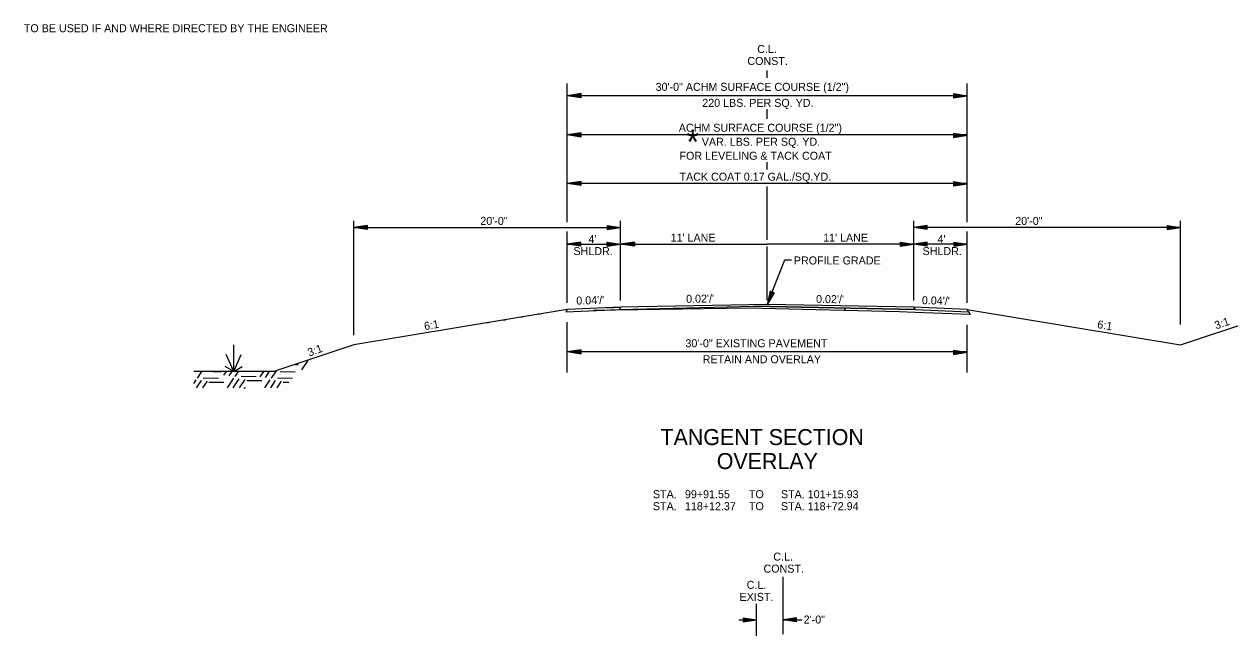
# Model space of a CAD drawing. Extents: x -900 to 15312, y 1857 to 2945.
# Drawn here: x 1572 to 2476, y 2439 to 2897 of the extents above; entities that cross this region are included whole.
import ezdxf

# ---------------------------------------------------------------- set-up
doc = ezdxf.new("R2010")
doc.units = 0
for name, color, linetype in [('R_Annotation', 7, 'Continuous'), ('R_Centerline', 7, 'Continuous'), ('R_Dimension', 7, 'Continuous'), ('R_Draft', 7, 'Continuous')]:
    doc.layers.add(name, color=color, linetype=linetype)

msp = doc.modelspace()

# ---------------------------------------------------------------- linework, layer by layer
at = {"layer": 'R_Annotation'}
for p, q in [((2239.93, 2683.31), (2119.09, 2685.72)), ((2239.09, 2684.99), (2129.09, 2687.19)), ((1979.08, 2683.39), (1819.08, 2656.72)), ((2009.09, 2684.59), (2019.09, 2684.99)), ((2019.09, 2684.99), (2018.23, 2683.27)), ((2279.09, 2683.39), (2239.09, 2684.99)), ((2239.09, 2684.99), (2239.93, 2683.31)), ((2279.09, 2683.39), (2439.09, 2656.72)), ((2439.09, 2656.72), (2499.09, 2676.72)), ((1819.08, 2656.72), (1759.08, 2636.72)), ((1759.08, 2636.72), (1699.08, 2636.72))]:
    msp.add_line(p, q, dxfattribs=at)
for points in [[(1939.32, 2676.76), (1939.32, 2676.75), (1939.32, 2676.72), (1939.32, 2676.7), (1939.32, 2676.69)], [(1939.38, 2676.69), (1939.38, 2676.7), (1939.38, 2676.73), (1939.38, 2676.75), (1939.39, 2676.77)], [(1945.88, 2677.86), (1945.83, 2677.84), (1945.5, 2677.73), (1945.17, 2677.65), (1944.75, 2677.62), (1944.63, 2677.62), (1944.5, 2677.63)], [(1947, 2677.97), (1947.02, 2677.97), (1947.04, 2677.97), (1947.06, 2677.97)], [(1957.24, 2679.73), (1957.22, 2679.73), (1957.17, 2679.73), (1957.13, 2679.73), (1957.12, 2679.73)], [(1958.72, 2680), (1958.64, 2679.96), (1958.28, 2679.84), (1957.91, 2679.74), (1957.5, 2679.72), (1957.37, 2679.72), (1957.24, 2679.73)], [(1959.57, 2680.14), (1959.64, 2680.14), (1959.72, 2680.14), (1959.8, 2680.13)], [(1964.92, 2681.03), (1964.92, 2681.03), (1964.92, 2681.03), (1964.92, 2681.03)], [(1964.98, 2681.03), (1964.98, 2681.03), (1964.98, 2681.04), (1964.98, 2681.04)], [(1970.83, 2682.01), (1970.78, 2682.01), (1970.73, 2682), (1970.68, 2681.99)], [(1972.6, 2682.31), (1972.6, 2682.31), (1972.6, 2682.31), (1972.6, 2682.31)], [(1972.6, 2682.31), (1972.62, 2682.31), (1972.64, 2682.31), (1972.66, 2682.31)], [(1913.7, 2672.49), (1913.71, 2672.45), (1913.72, 2672.41), (1913.72, 2672.36), (1913.72, 2672.36), (1913.72, 2672.35)], [(1920.55, 2673.64), (1920.42, 2673.57), (1920.28, 2673.51), (1919.86, 2673.38), (1919.57, 2673.31), (1919.14, 2673.28), (1918.9, 2673.28), (1918.68, 2673.3), (1918.59, 2673.31)], [(1921.4, 2673.63), (1921.42, 2673.63), (1921.44, 2673.63), (1921.46, 2673.63)], [(1931.64, 2675.39), (1931.62, 2675.39), (1931.46, 2675.39), (1931.31, 2675.4), (1931.19, 2675.41)], [(1933.36, 2675.77), (1933.2, 2675.69), (1933.05, 2675.62), (1932.6, 2675.48), (1932.31, 2675.4), (1931.9, 2675.38), (1931.77, 2675.38), (1931.64, 2675.39)], [(2346.47, 2672.01), (2346.46, 2672.02), (2346.43, 2672.08), (2346.41, 2672.13), (2346.4, 2672.17)]]:
    msp.add_open_spline(points, degree=3, dxfattribs=at)
at = {"layer": 'R_Centerline'}
for p, q in [((2129.09, 2857.11), (2129.09, 2862.4)), ((2129.09, 2826.19), (2129.09, 2833.59)), ((2129.09, 2788.18), (2129.09, 2793.83)), ((2129.09, 2735.56), (2129.09, 2775.55)), ((2129.09, 2690.25), (2129.09, 2730.54)), ((2141.18, 2439.91), (2141.18, 2482.86)), ((2121.18, 2438.65), (2121.18, 2462.72))]:
    msp.add_line(p, q, dxfattribs=at)
at = {"layer": 'R_Dimension'}
for p, q in [((1979.08, 2748.81), (1979.08, 2852.68)), ((2279.09, 2748.81), (2279.09, 2852.68)), ((1989.49, 2845.16), (1979.08, 2843.6)), ((2279.09, 2843.6), (1979.08, 2843.6)), ((1989.49, 2842.04), (1979.08, 2843.6)), ((1989.49, 2844.9), (1980.82, 2843.6)), ((1989.49, 2842.3), (1980.82, 2843.6)), ((1989.49, 2844.63), (1982.61, 2843.6)), ((1989.49, 2842.57), (1982.61, 2843.6)), ((1989.49, 2844.37), (1984.34, 2843.6)), ((1989.49, 2842.83), (1984.34, 2843.6)), ((1989.49, 2844.11), (1986.11, 2843.6)), ((1989.49, 2843.1), (1986.11, 2843.6)), ((1989.49, 2843.84), (1987.84, 2843.6)), ((1989.49, 2843.36), (1987.84, 2843.6)), ((1989.49, 2842.04), (1989.49, 2845.16)), ((2268.68, 2845.16), (2279.09, 2843.6)), ((2268.68, 2845.16), (2268.68, 2842.04)), ((2268.68, 2844.9), (2277.35, 2843.6)), ((2268.68, 2844.63), (2275.56, 2843.6)), ((2268.68, 2844.37), (2273.83, 2843.6)), ((2268.68, 2844.1), (2272.06, 2843.6)), ((2268.68, 2843.84), (2270.32, 2843.6)), ((2268.68, 2842.04), (2279.09, 2843.6)), ((2268.68, 2843.09), (2272.06, 2843.6)), ((2268.68, 2842.57), (2275.56, 2843.6)), ((2268.68, 2842.3), (2277.35, 2843.6)), ((2268.68, 2842.83), (2273.83, 2843.6)), ((2268.68, 2843.36), (2270.32, 2843.6)), ((1989.49, 2815.75), (1979.08, 2814.19)), ((2279.09, 2814.19), (1979.08, 2814.19)), ((1989.49, 2812.63), (1979.08, 2814.19)), ((1989.49, 2815.49), (1980.82, 2814.19)), ((1989.49, 2812.89), (1980.82, 2814.19)), ((1989.49, 2815.22), (1982.61, 2814.19)), ((1989.49, 2813.16), (1982.61, 2814.19)), ((1989.49, 2814.96), (1984.34, 2814.19)), ((1989.49, 2813.42), (1984.34, 2814.19)), ((1989.49, 2814.7), (1986.11, 2814.19)), ((1989.49, 2813.69), (1986.11, 2814.19)), ((1989.49, 2814.43), (1987.84, 2814.19)), ((1989.49, 2813.95), (1987.84, 2814.19)), ((1989.49, 2812.63), (1989.49, 2815.75)), ((2268.81, 2815.51), (2279.21, 2813.94)), ((2268.81, 2815.51), (2268.81, 2812.38)), ((2268.81, 2815.25), (2277.47, 2813.94)), ((2268.81, 2814.97), (2275.68, 2813.94)), ((2268.81, 2814.71), (2273.96, 2813.94)), ((2268.81, 2814.44), (2272.19, 2813.94)), ((2268.81, 2814.18), (2270.45, 2813.94)), ((2268.81, 2812.38), (2279.21, 2813.94)), ((2268.81, 2813.43), (2272.19, 2813.94)), ((2268.81, 2812.91), (2275.68, 2813.94)), ((2268.81, 2812.64), (2277.47, 2813.94)), ((2268.81, 2813.17), (2273.96, 2813.94)), ((2268.81, 2813.71), (2270.45, 2813.94)), ((1989.49, 2779.4), (1979.08, 2777.84)), ((1989.49, 2776.28), (1979.08, 2777.84)), ((2279.09, 2777.84), (1979.08, 2777.84)), ((1989.49, 2779.14), (1980.82, 2777.84)), ((1989.49, 2776.54), (1980.82, 2777.84)), ((1989.49, 2778.87), (1982.61, 2777.84)), ((1989.49, 2776.81), (1982.61, 2777.84)), ((1989.49, 2778.61), (1984.34, 2777.84)), ((1989.49, 2777.07), (1984.34, 2777.84)), ((1989.49, 2778.35), (1986.11, 2777.84)), ((1989.49, 2777.34), (1986.11, 2777.84)), ((1989.49, 2778.08), (1987.84, 2777.84)), ((1989.49, 2777.6), (1987.84, 2777.84)), ((1989.49, 2776.28), (1989.49, 2779.4)), ((2019.09, 2777.84), (2017.82, 2777.84)), ((2268.68, 2779.16), (2279.09, 2777.6)), ((2268.68, 2779.16), (2268.68, 2776.04)), ((2268.68, 2778.9), (2277.35, 2777.6)), ((2268.68, 2778.63), (2275.56, 2777.6)), ((2268.68, 2778.37), (2273.83, 2777.6)), ((2268.68, 2778.1), (2272.06, 2777.6)), ((2268.68, 2777.84), (2270.32, 2777.6)), ((2268.68, 2776.04), (2279.09, 2777.6)), ((2268.68, 2777.09), (2272.06, 2777.6)), ((2268.68, 2776.57), (2275.56, 2777.6)), ((2268.68, 2776.3), (2277.35, 2777.6)), ((2268.68, 2776.83), (2273.83, 2777.6)), ((2268.68, 2777.36), (2270.32, 2777.6)), ((1819.08, 2664.19), (1819.08, 2749.82)), ((2019.09, 2732.32), (2019.09, 2749.82)), ((2239.09, 2732.32), (2239.09, 2749.82)), ((2439.09, 2671.99), (2439.09, 2749.82)), ((1829.08, 2746.32), (1819.08, 2744.82)), ((1829.08, 2743.32), (1819.08, 2744.82)), ((1819.08, 2744.82), (2019.09, 2744.82)), ((1829.08, 2746.07), (1820.75, 2744.82)), ((1829.08, 2743.57), (1820.75, 2744.82)), ((1829.08, 2745.82), (1822.47, 2744.82)), ((1829.08, 2743.83), (1822.47, 2744.82)), ((1829.08, 2745.57), (1824.14, 2744.82)), ((1829.08, 2744.08), (1824.14, 2744.82)), ((1829.08, 2745.31), (1825.83, 2744.82)), ((1829.08, 2744.33), (1825.83, 2744.82)), ((1829.08, 2745.06), (1827.5, 2744.82)), ((1829.08, 2744.59), (1827.5, 2744.82)), ((1829.08, 2746.32), (1829.08, 2743.32)), ((1979.08, 2688.4), (1979.08, 2741.68)), ((2009.09, 2746.32), (2019.09, 2744.82)), ((2009.09, 2746.32), (2009.09, 2743.32)), ((2009.09, 2746.07), (2017.42, 2744.82)), ((2009.09, 2745.82), (2015.7, 2744.82)), ((2009.09, 2745.57), (2014.03, 2744.82)), ((2009.09, 2745.31), (2012.34, 2744.82)), ((2009.09, 2745.06), (2010.67, 2744.82)), ((2009.09, 2743.32), (2019.09, 2744.82)), ((2009.09, 2744.33), (2012.34, 2744.82)), ((2009.09, 2743.83), (2015.7, 2744.82)), ((2009.09, 2743.57), (2017.42, 2744.82)), ((2009.09, 2744.08), (2014.03, 2744.82)), ((2009.09, 2744.59), (2010.67, 2744.82)), ((2249.09, 2746.32), (2239.09, 2744.82)), ((2249.09, 2743.32), (2239.09, 2744.82)), ((2439.09, 2744.82), (2239.09, 2744.82)), ((2249.09, 2746.07), (2240.76, 2744.82)), ((2249.09, 2743.57), (2240.76, 2744.82)), ((2249.09, 2745.82), (2242.48, 2744.82)), ((2249.09, 2743.83), (2242.48, 2744.82)), ((2249.09, 2745.57), (2244.14, 2744.82)), ((2249.09, 2744.08), (2244.14, 2744.82)), ((2249.09, 2745.31), (2245.84, 2744.82)), ((2249.09, 2744.34), (2245.84, 2744.82)), ((2249.09, 2745.06), (2247.51, 2744.82)), ((2249.09, 2744.59), (2247.51, 2744.82)), ((2249.09, 2743.32), (2249.09, 2746.32)), ((2279.09, 2688.4), (2279.09, 2741.68)), ((2429.09, 2746.32), (2439.09, 2744.82)), ((2429.09, 2746.32), (2429.09, 2743.32)), ((2429.09, 2746.07), (2437.42, 2744.82)), ((2429.09, 2745.82), (2435.7, 2744.82)), ((2429.09, 2745.57), (2434.03, 2744.82)), ((2429.09, 2745.31), (2432.34, 2744.82)), ((2429.09, 2745.06), (2430.67, 2744.82)), ((2429.09, 2743.32), (2439.09, 2744.82)), ((2429.09, 2744.33), (2432.34, 2744.82)), ((2429.09, 2743.83), (2435.7, 2744.82)), ((2429.09, 2743.57), (2437.42, 2744.82)), ((2429.09, 2744.08), (2434.03, 2744.82)), ((2429.09, 2744.59), (2430.67, 2744.82)), ((1979.08, 2732.32), (2129.09, 2732.32)), ((1979.09, 2692.16), (1979.09, 2735.32)), ((1989.09, 2733.82), (1979.09, 2732.32)), ((1989.09, 2730.82), (1979.09, 2732.32)), ((1989.09, 2733.57), (1980.76, 2732.32)), ((1989.09, 2731.07), (1980.76, 2732.32)), ((1989.09, 2733.32), (1982.48, 2732.32)), ((1989.09, 2731.33), (1982.48, 2732.32)), ((1989.09, 2733.07), (1984.14, 2732.32)), ((1989.09, 2731.58), (1984.14, 2732.32)), ((1989.09, 2732.81), (1985.84, 2732.32)), ((1989.09, 2731.83), (1985.84, 2732.32)), ((1989.09, 2732.56), (1987.51, 2732.32)), ((1989.09, 2732.09), (1987.51, 2732.32)), ((1989.09, 2733.82), (1989.09, 2730.82)), ((2009.09, 2733.82), (2019.09, 2732.32)), ((2009.09, 2730.82), (2009.09, 2733.82)), ((2009.09, 2733.57), (2017.42, 2732.32)), ((2009.09, 2733.32), (2015.7, 2732.32)), ((2009.09, 2733.07), (2014.03, 2732.32)), ((2009.09, 2732.81), (2012.34, 2732.32)), ((2009.09, 2732.56), (2010.67, 2732.32)), ((2009.09, 2730.82), (2019.09, 2732.32)), ((2009.09, 2731.84), (2012.34, 2732.32)), ((2009.09, 2731.33), (2015.7, 2732.32)), ((2009.09, 2731.07), (2017.42, 2732.32)), ((2009.09, 2731.58), (2014.03, 2732.32)), ((2009.09, 2732.09), (2010.67, 2732.32)), ((2019.09, 2690), (2019.09, 2734.82)), ((2029.49, 2733.88), (2019.09, 2732.32)), ((2029.49, 2730.76), (2019.09, 2732.32)), ((2029.49, 2733.62), (2020.82, 2732.32)), ((2029.49, 2731.02), (2020.82, 2732.32)), ((2029.49, 2733.35), (2022.61, 2732.32)), ((2029.49, 2731.29), (2022.61, 2732.32)), ((2029.49, 2733.09), (2024.34, 2732.32)), ((2029.49, 2731.55), (2024.34, 2732.32)), ((2029.49, 2732.82), (2026.11, 2732.32)), ((2029.49, 2731.81), (2026.11, 2732.32)), ((2029.49, 2732.56), (2027.85, 2732.32)), ((2029.49, 2732.08), (2027.85, 2732.32)), ((2029.49, 2733.88), (2029.49, 2730.76)), ((2279.09, 2732.32), (2129.09, 2732.32)), ((2228.68, 2733.88), (2239.09, 2732.32)), ((2228.68, 2733.88), (2228.68, 2730.76)), ((2228.68, 2733.62), (2237.35, 2732.32)), ((2228.68, 2733.35), (2235.56, 2732.32)), ((2228.68, 2733.09), (2233.83, 2732.32)), ((2228.68, 2732.82), (2232.06, 2732.32)), ((2228.68, 2732.56), (2230.32, 2732.32)), ((2228.68, 2730.76), (2239.09, 2732.32)), ((2228.68, 2731.81), (2232.06, 2732.32)), ((2228.68, 2731.29), (2235.56, 2732.32)), ((2228.68, 2731.02), (2237.35, 2732.32)), ((2228.68, 2731.55), (2233.83, 2732.32)), ((2228.68, 2732.08), (2230.32, 2732.32)), ((2239.09, 2690), (2239.09, 2734.82)), ((2249.09, 2733.82), (2239.09, 2732.32)), ((2249.09, 2730.82), (2239.09, 2732.32)), ((2249.09, 2733.57), (2240.76, 2732.32)), ((2249.09, 2731.07), (2240.76, 2732.32)), ((2249.09, 2733.32), (2242.48, 2732.32)), ((2249.09, 2731.33), (2242.48, 2732.32)), ((2249.09, 2733.07), (2244.14, 2732.32)), ((2249.09, 2731.58), (2244.14, 2732.32)), ((2249.09, 2732.81), (2245.84, 2732.32)), ((2249.09, 2731.84), (2245.84, 2732.32)), ((2249.09, 2732.56), (2247.51, 2732.32)), ((2249.09, 2732.09), (2247.51, 2732.32)), ((2249.09, 2730.82), (2249.09, 2733.82)), ((2269.09, 2733.82), (2279.09, 2732.32)), ((2269.09, 2733.82), (2269.09, 2730.82)), ((2269.09, 2733.57), (2277.42, 2732.32)), ((2269.09, 2733.32), (2275.7, 2732.32)), ((2269.09, 2733.07), (2274.03, 2732.32)), ((2269.09, 2732.81), (2272.34, 2732.32)), ((2269.09, 2732.56), (2270.67, 2732.32)), ((2269.09, 2730.82), (2279.09, 2732.32)), ((2269.09, 2731.83), (2272.34, 2732.32)), ((2269.09, 2731.33), (2275.7, 2732.32)), ((2269.09, 2731.07), (2277.42, 2732.32)), ((2269.09, 2731.58), (2274.03, 2732.32)), ((2269.09, 2732.09), (2270.67, 2732.32)), ((2279.09, 2692.16), (2279.09, 2735.32)), ((2131.42, 2697.03), (2129.09, 2687.19)), ((2134.21, 2695.91), (2129.09, 2687.19)), ((2131.66, 2696.94), (2129.71, 2688.74)), ((2133.98, 2696), (2129.71, 2688.74)), ((2131.89, 2696.84), (2130.35, 2690.34)), ((2133.74, 2696.1), (2130.35, 2690.34)), ((2132.13, 2696.75), (2130.97, 2691.88)), ((2133.51, 2696.19), (2130.97, 2691.88)), ((2134.21, 2695.91), (2131.42, 2697.03)), ((2132.36, 2696.65), (2131.6, 2693.45)), ((2133.27, 2696.29), (2131.6, 2693.45)), ((2132.6, 2696.56), (2132.23, 2695)), ((2133.03, 2696.38), (2132.23, 2695)), ((2018.24, 2683.29), (2119.09, 2685.72)), ((2129.09, 2687.19), (2019.09, 2684.99)), ((2129.09, 2687.19), (2019.09, 2684.99)), ((2129.09, 2687.19), (2019.09, 2684.99)), ((2119.09, 2685.72), (2239.93, 2683.31)), ((2119.09, 2685.72), (2239.93, 2683.31)), ((2239.09, 2684.99), (2129.09, 2687.19)), ((2239.09, 2684.99), (2129.09, 2687.19)), ((2239.09, 2684.99), (2129.09, 2687.19)), ((2019.09, 2684.99), (2018.24, 2683.29)), ((2187.55, 2684.36), (2187.55, 2682.69)), ((2187.55, 2682.69), (2187.55, 2684.36)), ((2239.93, 2683.31), (2239.09, 2684.99)), ((2279.09, 2683.39), (2239.09, 2684.99)), ((2239.09, 2684.99), (2239.93, 2683.31)), ((2239.93, 2683.31), (2239.09, 2684.99)), ((2239.93, 2683.31), (2280.06, 2681.68)), ((2280.06, 2681.68), (2279.09, 2683.39)), ((1979.08, 2636.19), (1979.08, 2673.73)), ((2279.09, 2636.19), (2279.09, 2671.71)), ((1989.49, 2653.04), (1979.08, 2651.48)), ((2279.09, 2651.48), (1979.08, 2651.48)), ((1989.49, 2649.92), (1979.08, 2651.48)), ((1989.49, 2652.78), (1980.82, 2651.48)), ((1989.49, 2650.18), (1980.82, 2651.48)), ((1989.49, 2652.51), (1982.61, 2651.48)), ((1989.49, 2650.45), (1982.61, 2651.48)), ((1989.49, 2652.25), (1984.34, 2651.48)), ((1989.49, 2650.71), (1984.34, 2651.48)), ((1989.49, 2651.99), (1986.11, 2651.48)), ((1989.49, 2650.98), (1986.11, 2651.48)), ((1989.49, 2651.72), (1987.84, 2651.48)), ((1989.49, 2651.24), (1987.84, 2651.48)), ((1989.49, 2649.92), (1989.49, 2653.04)), ((2268.68, 2652.8), (2279.09, 2651.24)), ((2268.68, 2652.8), (2268.68, 2649.67)), ((2268.68, 2652.54), (2277.35, 2651.24)), ((2268.68, 2652.27), (2275.56, 2651.24)), ((2268.68, 2652.01), (2273.83, 2651.24)), ((2268.68, 2651.73), (2272.06, 2651.24)), ((2268.68, 2651.47), (2270.32, 2651.24)), ((2268.68, 2649.67), (2279.09, 2651.24)), ((2268.68, 2650.73), (2272.06, 2651.24)), ((2268.68, 2650.21), (2275.56, 2651.24)), ((2268.68, 2649.93), (2277.35, 2651.24)), ((2268.68, 2650.47), (2273.83, 2651.24)), ((2268.68, 2651), (2270.32, 2651.24)), ((1775.13, 2642.07), (1777.38, 2642.06)), ((1780.22, 2638.2), (1784.89, 2645.12)), ((1701.83, 2631.85), (1705.11, 2636.72)), ((1706.27, 2632.04), (1717.58, 2631.95)), ((1713.8, 2636.72), (1719.53, 2636.68)), ((1721.76, 2633.99), (1723.6, 2636.72)), ((1724.44, 2624.7), (1729.26, 2631.85)), ((1725.74, 2633.52), (1727.9, 2636.72)), ((1728.74, 2624.7), (1733.25, 2631.39)), ((1730.19, 2633.06), (1732.66, 2636.72)), ((1733.5, 2624.7), (1737.7, 2630.93)), ((1734.64, 2633.25), (1745.95, 2633.15)), ((1749.01, 2632.78), (1751.67, 2636.72)), ((1753, 2632.32), (1755.97, 2636.72)), ((1757.45, 2631.85), (1761.21, 2637.43)), ((1761.9, 2632.04), (1773.2, 2631.95)), ((1763.84, 2636.77), (1775.15, 2636.68)), ((1699.08, 2627.96), (1700.9, 2630.65)), ((1701.19, 2624.7), (1704.88, 2630.19)), ((1705.95, 2624.7), (1709.33, 2629.72)), ((1710.45, 2628.89), (1721.76, 2628.79)), ((1736.59, 2624.71), (1737.94, 2624.7)), ((1738.81, 2630.09), (1750.12, 2630)), ((1752.51, 2624.7), (1756.52, 2630.65)), ((1756.81, 2624.7), (1760.51, 2630.19)), ((1761.57, 2624.7), (1764.95, 2629.72)), ((1766.07, 2628.89), (1770.5, 2628.85)), ((2107.92, 2450.68), (2121.18, 2450.68)), ((2111.17, 2452.18), (2121.17, 2450.68)), ((2111.17, 2452.18), (2111.17, 2449.18)), ((2111.17, 2451.93), (2119.5, 2450.68)), ((2111.17, 2451.68), (2117.78, 2450.68)), ((2111.17, 2451.43), (2116.12, 2450.68)), ((2111.17, 2451.17), (2114.42, 2450.68)), ((2111.17, 2450.92), (2112.75, 2450.68)), ((2111.17, 2449.18), (2121.17, 2450.68)), ((2111.17, 2450.19), (2114.42, 2450.68)), ((2111.17, 2449.69), (2117.78, 2450.68)), ((2111.17, 2449.43), (2119.5, 2450.68)), ((2111.17, 2449.94), (2116.12, 2450.68)), ((2111.17, 2450.45), (2112.75, 2450.68)), ((2151.18, 2452.18), (2141.18, 2450.68)), ((2151.18, 2449.18), (2141.18, 2450.68)), ((2141.18, 2450.68), (2154.95, 2450.68)), ((2151.18, 2451.93), (2142.85, 2450.68)), ((2151.18, 2449.43), (2142.85, 2450.68)), ((2151.18, 2451.68), (2144.57, 2450.68)), ((2151.18, 2449.69), (2144.57, 2450.68)), ((2151.18, 2451.43), (2146.23, 2450.68)), ((2151.18, 2449.94), (2146.23, 2450.68)), ((2151.18, 2451.17), (2147.93, 2450.68)), ((2151.18, 2450.2), (2147.93, 2450.68)), ((2151.18, 2450.92), (2149.6, 2450.68)), ((2151.18, 2450.45), (2149.6, 2450.68)), ((2151.18, 2449.18), (2151.18, 2452.18))]:
    msp.add_line(p, q, dxfattribs=at)
for points in [[(2129.09, 2687.19), (2142.29, 2720.52), (2147.39, 2720.52)], [(1978.11, 2681.68), (2018.24, 2683.29), (2018.25, 2683.27), (2039.09, 2683.8), (2039.09, 2683.8), (2119.09, 2685.72)], [(2019.09, 2684.99), (1979.09, 2683.39), (1978.11, 2681.68)]]:
    msp.add_lwpolyline(points, dxfattribs=at)
msp.add_lwpolyline([(2239.93, 2683.31), (2280.06, 2681.68), (2281.31, 2679.51), (2240.05, 2681.16), (2228.21, 2681.45), (2165.76, 2683), (2115.15, 2684.26), (1998.94, 2682.52), (2018.24, 2683.29), (2119.09, 2685.72)], close=True, dxfattribs=at)
at = {"layer": 'R_Draft'}
for q in [(1723.39, 2649.65), (1729.08, 2656.81), (1734.78, 2649.65), (1722.79, 2640.51), (1735.37, 2640.51)]:
    msp.add_line((1729.08, 2636.72), q, dxfattribs=at)

# ---------------------------------------------------------------- texts
at = {"layer": 'R_Annotation'}
for s, height, p in [('TO BE USED IF AND WHERE DIRECTED BY THE ENGINEER', 6, (1571.76, 2891.17)), ('C.L.', 6, (2121.62, 2875.63)), ('CONST.', 6, (2114.25, 2866.63)), ('30\'-0" ACHM SURFACE COURSE (1/2")', 6, (2045.42, 2847.23)), ('220 LBS. PER SQ. YD.', 6, (2080.42, 2835.23)), ('ACHM SURFACE COURSE (1/2")', 6, (2062.8, 2816.58)), ('*', 18.39, (2068.5, 2799.79)), ('VAR. LBS. PER SQ. YD.', 6, (2080.05, 2806.08)), ('FOR LEVELING & TACK COAT', 6, (2063.35, 2795.58)), ('TACK COAT 0.17 GAL./SQ.YD.', 6, (2063.37, 2779.87)), ('20\'-0"', 6, (1914, 2746.73)), ('20\'-0"', 6, (2315.07, 2746.73)), ("11' LANE", 6, (2056.69, 2734.15)), ("11' LANE", 6, (2171.06, 2734.15)), ("4' ", 6, (1995.05, 2733.11)), ("4' ", 6, (2256.79, 2733.11)), ('SHLDR.', 6, (1983.85, 2724.11)), ('PROFILE GRADE', 6, (2149.08, 2717.08)), ('SHLDR.', 6, (2245.59, 2724.11)), ('30\'-0" EXISTING PAVEMENT', 6, (2067.79, 2655.02)), ('RETAIN AND OVERLAY', 6, (2080.71, 2643.02)), ('TANGENT SECTION', 12, (2049.1, 2581.7)), ('OVERLAY', 12, (2091.29, 2563.7)), ('STA. ', 6, (2043.4, 2541.87)), ('99+91.55 ', 6, (2067.4, 2541.87)), ('TO ', 6, (2115.4, 2541.87)), ('STA. 101+15.93', 6, (2139.4, 2541.87)), ('STA. ', 6, (2043.4, 2532.87)), ('118+12.37 ', 6, (2067.4, 2532.87)), ('TO ', 6, (2115.4, 2532.87)), ('STA. 118+72.94', 6, (2139.4, 2532.87)), ('C.L.', 6, (2133.71, 2495.07)), ('CONST.', 6, (2126.34, 2486.07)), ('C.L.', 6, (2113.71, 2473.89)), ('EXIST.', 6, (2108.37, 2464.89)), ('2\'-0"', 6, (2156.45, 2447.9))]:
    msp.add_text(s, height=height, dxfattribs=at).set_placement(p)
for s, rotation, p in [("0.02'/'", 0.64946, (2068.34, 2688.31)), ("0.02'/'", 359.35054, (2165.7, 2688.23)), ("0.04'/'", 1.60222, (1986.05, 2686.95)), ("0.04'/'", 358.39778, (2245, 2687.33)), ('3:1', 19.33935, (2465.74, 2668.32)), ('6:1', 9.97342, (1872.36, 2667.78)), ('6:1', 350.98474, (2376.3, 2669.42)), ('3:1', 19.62862, (1785.75, 2648))]:
    msp.add_text(s, height=6, rotation=rotation, dxfattribs=at).set_placement(p)

doc.saveas('drawing.dxf')
